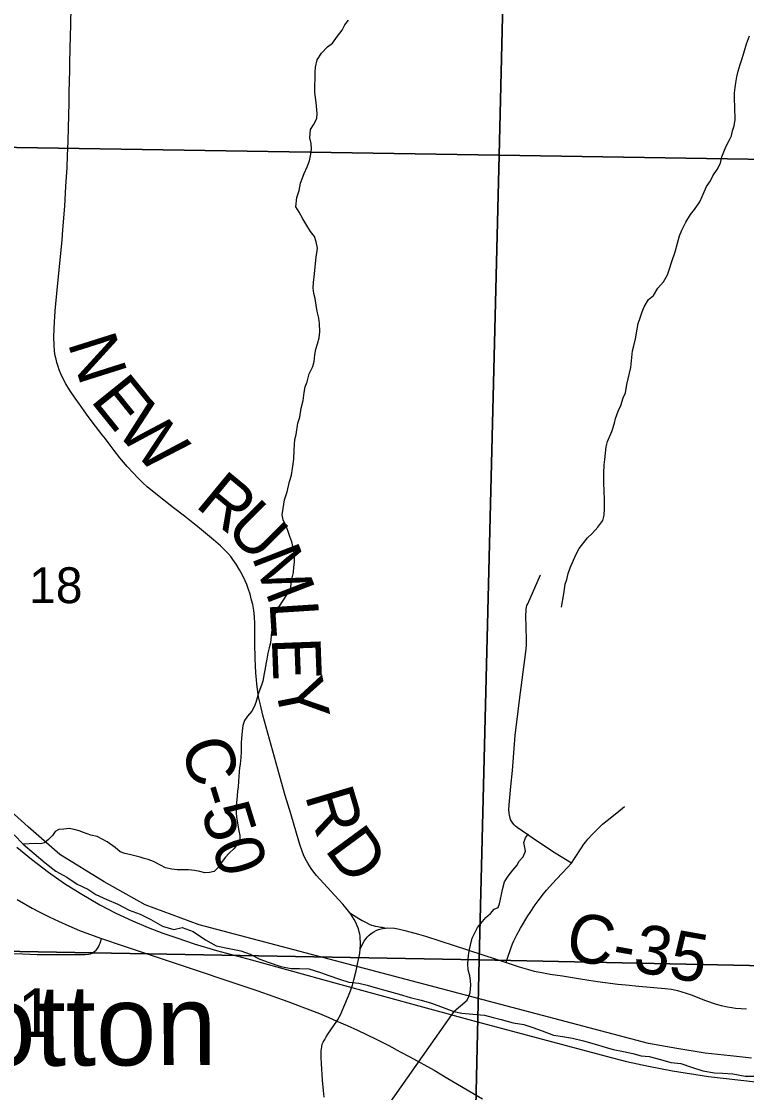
# Model space of a CAD drawing. Extents: x 0 to 34, y 0 to 22.
# Drawn here: x 12.938 to 13.784, y 17.845 to 19.096 of the extents above; entities that cross this region are included whole.
import ezdxf

# ---------------------------------------------------------------- set-up
doc = ezdxf.new("R2010")
doc.units = 0
for name, color, linetype in [('GM_X_Corporation', 7, 'Continuous'), ('GM_X_County_Road', 7, 'Continuous'), ('GM_X_County_Road_Text', 7, 'Continuous'), ('GM_X_Major_River', 7, 'Continuous'), ('GM_X_Major_River_Text', 7, 'Continuous'), ('GM_X_Minor_River', 7, 'Continuous'), ('GM_X_Rail_Line', 7, 'Continuous'), ('GM_X_Section_Text', 7, 'Continuous'), ('GM_X_State_Route', 7, 'Continuous'), ('GM_X_Township_Road', 7, 'Continuous'), ('GM_X_Township_Road_Text', 7, 'Continuous')]:
    doc.layers.add(name, color=color, linetype=linetype)

msp = doc.modelspace()

# ---------------------------------------------------------------- linework, layer by layer
at = {"layer": 'GM_X_Corporation'}
for points in [[(13.52, 19.9573), (13.4956, 18.9396), (12.4906, 18.9558), (12.5051, 19.9749)], [(14.532, 19.9321), (14.5125, 18.9236), (13.4956, 18.9396), (13.52, 19.9573)], [(12.4906, 18.9558), (13.4956, 18.9396), (13.4723, 18.0001), (12.4638, 18.0185)], [(13.4956, 18.9396), (14.5125, 18.9236), (14.4926, 17.9788), (13.4723, 18.0001)], [(12.4638, 18.0185), (13.4723, 18.0001), (13.4493, 16.9912), (12.4446, 17.0089)], [(13.4723, 18.0001), (14.4926, 17.9788), (14.4709, 16.9847), (13.4493, 16.9912)]]:
    msp.add_lwpolyline(points, close=True, dxfattribs=at)
at = {"layer": 'GM_X_County_Road'}
for points in [[(13.2879, 17.8943), (13.288, 17.8961), (13.2884, 17.8992), (13.2891, 17.9017), (13.2902, 17.9042), (13.2919, 17.9074), (13.2935, 17.9103), (13.2956, 17.9135), (13.3059, 17.9286), (13.3075, 17.9311), (13.3088, 17.9334), (13.3102, 17.936), (13.3143, 17.9452), (13.3197, 17.9581), (13.3219, 17.9641), (13.3242, 17.9706), (13.3259, 17.9768), (13.3287, 17.9874), (13.3307, 17.9973), (13.3324, 18.0059), (13.3327, 18.008), (13.3332, 18.0126), (13.3336, 18.0183), (13.3333, 18.0277), (13.3329, 18.0301), (13.3323, 18.033), (13.3312, 18.0365), (13.3298, 18.04), (13.3282, 18.0437), (13.3263, 18.0472), (13.3225, 18.0534), (13.3212, 18.0552), (13.3151, 18.0628), (13.3129, 18.0653), (13.2991, 18.0803), (13.2823, 18.0987), (13.2791, 18.1028), (13.2762, 18.1067), (13.2722, 18.1131), (13.2692, 18.1184), (13.2671, 18.123), (13.2655, 18.1273), (13.2628, 18.1351), (13.259, 18.1483), (13.2527, 18.1695), (13.2459, 18.192), (13.2412, 18.2089), (13.2197, 18.2859), (13.2169, 18.2981), (13.2148, 18.3075), (13.2134, 18.3164), (13.2127, 18.3223), (13.2121, 18.3276), (13.2115, 18.3349), (13.2107, 18.3524), (13.2104, 18.3691), (13.2103, 18.3929), (13.2099, 18.4008), (13.2091, 18.4082), (13.2079, 18.4152), (13.2066, 18.4202), (13.2047, 18.4273), (13.2031, 18.4325), (13.2009, 18.4385), (13.1991, 18.4428), (13.1956, 18.4501), (13.1924, 18.4558), (13.1884, 18.4624), (13.1847, 18.4677), (13.1822, 18.471), (13.1788, 18.4749), (13.1746, 18.4794), (13.1701, 18.4837), (13.1622, 18.4907), (13.1457, 18.5041), (13.1281, 18.5183), (13.1152, 18.528), (13.0948, 18.5442), (13.0848, 18.5525), (13.0797, 18.5571), (13.073, 18.5637), (13.0686, 18.5684), (13.0612, 18.5761), (13.0527, 18.5864), (13.046, 18.5951), (13.0414, 18.6011), (13.036, 18.6084), (13.0323, 18.6133), (13.0245, 18.6234), (13.0159, 18.6348), (13.011, 18.6413), (13.0055, 18.6489), (13.0005, 18.6559), (12.9939, 18.6658), (12.9897, 18.6728), (12.987, 18.6778), (12.9838, 18.6845), (12.982, 18.6891), (12.9806, 18.6932), (12.9792, 18.6978), (12.9783, 18.7017), (12.9774, 18.7055), (12.9766, 18.7108), (12.976, 18.7179), (12.9758, 18.7278), (12.9764, 18.7457), (12.9768, 18.7506), (12.9773, 18.7579), (12.98, 18.7865), (12.9854, 18.8407), (12.9864, 18.8525), (12.9884, 18.8803), (12.9897, 18.9032), (12.9912, 18.9252), (12.9916, 18.9392), (12.9923, 18.9556), (12.9929, 18.9719), (12.9932, 18.9858), (12.9935, 19.0016), (12.9937, 19.0131), (12.994, 19.0266), (12.9943, 19.0387), (12.9943, 19.0471), (12.9946, 19.0646), (12.995, 19.0784), (12.9954, 19.0923), (12.9962, 19.1338)], [(13.3212, 18.0552), (13.3231, 18.054), (13.3255, 18.0525), (13.3316, 18.0487), (13.3355, 18.0463), (13.3404, 18.0437), (13.3439, 18.042), (13.3467, 18.0409), (13.3484, 18.0403), (13.3508, 18.0396), (13.3539, 18.039), (13.357, 18.0385), (13.3591, 18.0382), (13.363, 18.0374)], [(13.3332, 18.0126), (13.335, 18.0161), (13.338, 18.0221), (13.34, 18.0249), (13.3419, 18.0271), (13.3439, 18.0292), (13.3461, 18.031), (13.3493, 18.033), (13.3519, 18.0346), (13.3548, 18.0358), (13.3578, 18.0366), (13.3593, 18.037), (13.3618, 18.0373), (13.363, 18.0374), (13.3654, 18.0375), (13.3733, 18.0371), (13.3791, 18.0361), (13.3855, 18.0345), (13.3914, 18.0331), (13.4015, 18.0302), (13.4094, 18.0278), (13.4431, 18.017), (13.4585, 18.0121), (13.4764, 18.0062), (13.492, 18.0011), (13.5038, 17.9972), (13.519, 17.9921), (13.5297, 17.9889), (13.5362, 17.9872), (13.5452, 17.9854), (13.5552, 17.9836), (13.5696, 17.9814), (13.5903, 17.9782), (13.6001, 17.9766), (13.6103, 17.975), (13.6339, 17.972), (13.6433, 17.9709), (13.6586, 17.9696), (13.6892, 17.9669), (13.6966, 17.966), (13.7036, 17.9644), (13.7089, 17.963), (13.7139, 17.9612), (13.7195, 17.9594), (13.7365, 17.9529), (13.7488, 17.9485), (13.7547, 17.9469), (13.762, 17.9453), (13.767, 17.9444), (13.7715, 17.9438), (13.7779, 17.9433), (13.7844, 17.943)], [(13.2911, 17.8399), (13.2904, 17.8477), (13.2895, 17.8597), (13.2881, 17.8791), (13.2878, 17.8861), (13.2879, 17.8943)]]:
    msp.add_lwpolyline(points, dxfattribs=at)
at = {"layer": 'GM_X_Major_River'}
msp.add_lwpolyline([(12.9293, 18.1462), (12.9401, 18.1353), (12.9528, 18.1245), (12.9655, 18.1134), (12.9782, 18.1037), (12.9908, 18.0967), (13.003, 18.0886), (13.0153, 18.0827), (13.0248, 18.0764), (13.0375, 18.0706), (13.0504, 18.0651), (13.0638, 18.0581), (13.0764, 18.0534), (13.089, 18.0475), (13.1024, 18.0394), (13.1157, 18.0358), (13.1256, 18.0379), (13.1385, 18.0332), (13.1527, 18.0235), (13.1653, 18.0165), (13.1802, 18.0134), (13.1938, 18.0109), (13.2049, 18.0069), (13.216, 18.0011), (13.2259, 17.9974), (13.2408, 17.9924), (13.2529, 17.9903), (13.2624, 17.9901), (13.2734, 17.9899), (13.2868, 17.9855), (13.2967, 17.9819), (13.3092, 17.9776), (13.3199, 17.974), (13.3317, 17.973), (13.3416, 17.9705), (13.3534, 17.9673), (13.3675, 17.9634), (13.3789, 17.9601), (13.3915, 17.9562), (13.4044, 17.953), (13.4166, 17.9498), (13.4303, 17.9447), (13.4425, 17.9399), (13.452, 17.9378), (13.4646, 17.9369), (13.4786, 17.9356), (13.4885, 17.9331), (13.498, 17.9306), (13.5117, 17.9267), (13.5243, 17.9246), (13.5349, 17.9214), (13.5456, 17.9174), (13.559, 17.9123), (13.5696, 17.9106), (13.581, 17.9089), (13.594, 17.9057), (13.6065, 17.9021), (13.6191, 17.8981), (13.6286, 17.8956), (13.6408, 17.8932), (13.6514, 17.8907), (13.6613, 17.8882), (13.6708, 17.8872), (13.6838, 17.884), (13.696, 17.8804), (13.7074, 17.8791), (13.7199, 17.8751), (13.7333, 17.8708), (13.7469, 17.8684), (13.7564, 17.8678), (13.7682, 17.8672), (13.7826, 17.8644), (13.7936, 17.8646)], dxfattribs=at)
at = {"layer": 'GM_X_Minor_River'}
for points in [[(13.2348, 18.4064), (13.2518, 18.4332), (13.2534, 18.4449), (13.2553, 18.4525), (13.2557, 18.4586), (13.2565, 18.4647), (13.2566, 18.4738), (13.2536, 18.4883), (13.251, 18.4947), (13.2491, 18.5004), (13.2468, 18.5065), (13.2434, 18.5138), (13.2423, 18.5198), (13.2435, 18.5274), (13.2451, 18.5373), (13.2481, 18.5468), (13.2509, 18.5586), (13.2532, 18.5662), (13.2543, 18.5738), (13.2559, 18.5848), (13.2563, 18.5954), (13.2571, 18.6076), (13.2587, 18.6136), (13.2606, 18.6269), (13.2629, 18.6338), (13.2645, 18.6444), (13.2668, 18.6535), (13.268, 18.6626), (13.2692, 18.6691), (13.2715, 18.6751), (13.2738, 18.6843), (13.278, 18.693), (13.2795, 18.6987), (13.2803, 18.7067), (13.2815, 18.7131), (13.2834, 18.7196), (13.2853, 18.7264), (13.2861, 18.7336), (13.2858, 18.7431), (13.2851, 18.7496), (13.2836, 18.7557), (13.2825, 18.7621), (13.2806, 18.7724), (13.2791, 18.7781), (13.2784, 18.7846), (13.2788, 18.791), (13.28, 18.8013), (13.2808, 18.8093), (13.282, 18.8206), (13.2835, 18.8313), (13.282, 18.8385), (13.2798, 18.845), (13.2753, 18.8507), (13.2711, 18.8575), (13.2662, 18.8655), (13.2621, 18.8732), (13.2583, 18.8796), (13.2595, 18.8903), (13.2622, 18.8986), (13.2637, 18.907), (13.268, 18.9184), (13.2714, 18.9263), (13.2741, 18.9332), (13.2756, 18.9411), (13.2764, 18.9468), (13.2761, 18.9533), (13.2746, 18.9601), (13.2754, 18.9696), (13.2788, 18.9753), (13.2827, 18.9825), (13.2831, 18.9886), (13.282, 19.0011), (13.2805, 19.0129), (13.2802, 19.0201), (13.2806, 19.03), (13.2806, 19.0369), (13.281, 19.0426), (13.283, 19.0509), (13.2883, 19.0589), (13.2952, 19.0664), (13.3009, 19.0706), (13.307, 19.0789), (13.3123, 19.0858), (13.3154, 19.0918), (13.3196, 19.0975)], [(13.5682, 18.4119), (13.5709, 18.4275), (13.5725, 18.4388), (13.5744, 18.4445), (13.5759, 18.4514), (13.5783, 18.4578), (13.5851, 18.473), (13.589, 18.4806), (13.5985, 18.4931), (13.6042, 18.498), (13.6107, 18.5056), (13.6164, 18.5132), (13.618, 18.5196), (13.6184, 18.5268), (13.6184, 18.5371), (13.6181, 18.5485), (13.6178, 18.5561), (13.6178, 18.5686), (13.6182, 18.5781), (13.619, 18.5846), (13.6198, 18.5918), (13.6206, 18.5994), (13.6218, 18.6055), (13.6271, 18.6172), (13.6302, 18.6267), (13.6314, 18.6324), (13.6344, 18.6408), (13.6375, 18.6476), (13.6402, 18.6563), (13.6429, 18.6624), (13.6444, 18.6719), (13.646, 18.6787), (13.6491, 18.692), (13.6511, 18.7114), (13.6526, 18.7171), (13.6545, 18.7254), (13.6565, 18.7368), (13.6576, 18.7433), (13.66, 18.7497), (13.6626, 18.7569), (13.6649, 18.7626), (13.6699, 18.7714), (13.6756, 18.7759), (13.6806, 18.7846), (13.6875, 18.7918), (13.692, 18.8002), (13.6943, 18.807), (13.697, 18.8157), (13.7009, 18.8271), (13.7036, 18.837), (13.7059, 18.8457), (13.7086, 18.8522), (13.7136, 18.8616), (13.7189, 18.8704), (13.7235, 18.8764), (13.7296, 18.8851), (13.7323, 18.8916), (13.7376, 18.903), (13.7422, 18.9098), (13.7449, 18.9155), (13.7499, 18.9231), (13.7537, 18.9303), (13.7556, 18.9379), (13.7602, 18.9496), (13.7641, 18.9568), (13.7667, 18.9625), (13.7679, 18.9682), (13.7698, 18.9739), (13.771, 18.9815), (13.7707, 18.9956), (13.7703, 19.0062), (13.7704, 19.0127), (13.7711, 19.0187), (13.7719, 19.0244), (13.7731, 19.0313), (13.7746, 19.0377), (13.777, 19.0457), (13.7789, 19.0514), (13.7808, 19.0579), (13.7843, 19.0696), (13.7877, 19.0791)], [(13.2348, 18.4064), (13.2329, 18.4003), (13.2311, 18.3881), (13.2299, 18.3828), (13.2285, 18.3703), (13.227, 18.3646), (13.2255, 18.3585), (13.2244, 18.3513), (13.2232, 18.3456), (13.2225, 18.3406), (13.2214, 18.3346), (13.2195, 18.3258), (13.218, 18.3209), (13.2161, 18.3159), (13.2142, 18.3106), (13.2131, 18.3061), (13.2116, 18.3008), (13.2097, 18.2958), (13.2067, 18.2905), (13.2018, 18.2848), (13.1984, 18.2798), (13.1965, 18.2738), (13.1954, 18.2673), (13.1947, 18.2586), (13.1943, 18.254), (13.1944, 18.2434), (13.194, 18.2365), (13.1933, 18.2289), (13.1925, 18.2244), (13.1922, 18.2198), (13.1918, 18.2145), (13.1914, 18.2088), (13.1907, 18.202), (13.19, 18.1974), (13.1896, 18.1917), (13.1885, 18.1796), (13.1885, 18.172), (13.1889, 18.1667), (13.1916, 18.1507), (13.1928, 18.1454), (13.1928, 18.1409), (13.1898, 18.1348), (13.1864, 18.1302), (13.1803, 18.1249), (13.1758, 18.1199), (13.1713, 18.1139), (13.1683, 18.1089), (13.163, 18.1032), (13.1576, 18.1024), (13.1519, 18.102), (13.1463, 18.1032), (13.1398, 18.1047), (13.133, 18.1054), (13.1197, 18.1054), (13.1136, 18.1061), (13.106, 18.1077), (13.1003, 18.1107), (13.0919, 18.1152), (13.0858, 18.1175), (13.0813, 18.1186), (13.0763, 18.1201), (13.0642, 18.1231), (13.0585, 18.1243), (13.0532, 18.1265), (13.0474, 18.1315), (13.0379, 18.1379), (13.0261, 18.1443), (13.0189, 18.1459), (13.0105, 18.1489), (13.0052, 18.1508), (12.9995, 18.1523), (12.9935, 18.1534), (12.9874, 18.153), (12.9817, 18.1526), (12.9771, 18.1499), (12.9741, 18.1454), (12.9696, 18.1408), (12.9647, 18.137), (12.9601, 18.1355), (12.954, 18.1362), (12.9401, 18.1353)], [(13.4425, 17.9399), (13.4581, 17.953), (13.46, 17.9576), (13.4615, 17.9621), (13.4626, 17.9705), (13.4622, 17.9762), (13.4614, 17.9815), (13.4595, 17.9887), (13.4591, 17.9955), (13.4598, 18.0058), (13.4609, 18.0122), (13.462, 18.0172), (13.4639, 18.0255), (13.4677, 18.0324), (13.4703, 18.0381), (13.476, 18.0449), (13.4798, 18.0495), (13.4855, 18.0544), (13.4896, 18.0594), (13.4942, 18.0613), (13.496, 18.0658), (13.4983, 18.0765), (13.4994, 18.0822), (13.5017, 18.0913), (13.5062, 18.0978), (13.5115, 18.105), (13.5164, 18.1107), (13.5183, 18.1152), (13.5236, 18.1206), (13.5262, 18.127), (13.5254, 18.1316), (13.5243, 18.1373), (13.5262, 18.1426), (13.5296, 18.1475)], [(13.4425, 17.9399), (13.3436, 17.7994)]]:
    msp.add_lwpolyline(points, dxfattribs=at)
at = {"layer": 'GM_X_Rail_Line'}
for points in [[(13.7901, 17.8853), (13.7655, 17.888), (13.736, 17.8911), (13.7029, 17.8967), (13.67, 17.9025), (13.1455, 18.041), (13.0824, 18.0646), (13.0345, 18.0914), (12.9829, 18.1233), (12.9459, 18.1554), (12.8969, 18.1997)], [(12.9327, 18.1319), (12.9496, 18.1177), (12.9694, 18.1025), (12.988, 18.0894), (13.0063, 18.0779), (13.0295, 18.0645), (13.0481, 18.0548), (13.0674, 18.0457), (13.0857, 18.038), (13.1031, 18.0312), (13.1192, 18.0258), (13.1394, 18.019), (13.1657, 18.0112), (13.2064, 18.0001), (13.3021, 17.9738), (13.4644, 17.9296), (13.6203, 17.8876), (13.6443, 17.8816), (13.6697, 17.876), (13.6979, 17.8706), (13.74, 17.864), (13.7948, 17.8578)]]:
    msp.add_lwpolyline(points, dxfattribs=at)
at = {"layer": 'GM_X_State_Route'}
msp.add_lwpolyline([(12.9328, 18.0705), (12.9504, 18.0607), (12.9587, 18.0561), (12.971, 18.0499), (12.9813, 18.0452), (12.9933, 18.0398), (13.0057, 18.0346), (13.0175, 18.0301), (13.0315, 18.0251), (13.0567, 18.0165), (13.1348, 17.9905), (13.1869, 17.9731), (13.2137, 17.9642), (13.249, 17.9517), (13.2684, 17.9442), (13.2857, 17.9375), (13.2969, 17.9328), (13.3059, 17.9286), (13.3183, 17.9235), (13.3302, 17.918), (13.3519, 17.9076), (13.3667, 17.9001), (13.38, 17.893), (13.3914, 17.887), (13.4195, 17.8713), (13.4358, 17.8617), (13.4761, 17.8379)], dxfattribs=at)
at = {"layer": 'GM_X_Township_Road'}
for points in [[(13.5798, 18.1131), (13.561, 18.1246), (13.5404, 18.1384), (13.5165, 18.1546), (13.5144, 18.1563), (13.513, 18.1577), (13.5114, 18.1597), (13.5099, 18.162), (13.5089, 18.164), (13.5082, 18.1662), (13.5076, 18.1687), (13.5071, 18.1717), (13.5069, 18.1755), (13.5073, 18.1812), (13.508, 18.1897), (13.5092, 18.2025), (13.5109, 18.2214), (13.5134, 18.2522), (13.5143, 18.2626), (13.5164, 18.281), (13.5193, 18.3036), (13.5266, 18.3597), (13.5273, 18.3673), (13.5274, 18.3732), (13.527, 18.3894), (13.5267, 18.4013), (13.527, 18.4094), (13.5273, 18.4121), (13.5279, 18.4139), (13.5288, 18.416), (13.5439, 18.4499)], [(13.5038, 17.9972), (13.505, 18.0012), (13.5094, 18.0148), (13.5109, 18.0188), (13.5125, 18.0225), (13.5163, 18.0296), (13.5206, 18.0371), (13.5291, 18.0515), (13.5316, 18.0555), (13.5376, 18.0645), (13.541, 18.0691), (13.5472, 18.0773), (13.5507, 18.0816), (13.5581, 18.0899), (13.5619, 18.094), (13.5699, 18.1022), (13.5798, 18.1131), (13.5836, 18.1185), (13.5917, 18.1311), (13.5943, 18.1352), (13.5965, 18.1382), (13.599, 18.1413), (13.604, 18.1465), (13.6121, 18.1546), (13.6163, 18.1585), (13.6216, 18.1629), (13.6327, 18.1717), (13.6419, 18.1792)], [(12.9155, 18.0079), (12.9391, 18.0071), (12.9563, 18.0066), (13.0065, 18.0063), (13.0121, 18.0065), (13.0162, 18.0069), (13.0185, 18.0074), (13.0206, 18.0082), (13.0221, 18.0091), (13.0237, 18.0103), (13.0251, 18.0117), (13.0266, 18.0136), (13.0279, 18.0156), (13.0291, 18.0182), (13.0298, 18.0199), (13.031, 18.0235), (13.0315, 18.0251)]]:
    msp.add_lwpolyline(points, dxfattribs=at)

# ---------------------------------------------------------------- texts
at = {"layer": 'GM_X_County_Road_Text'}
for s, height, rotation, p in [('N', 0.0568, 287.5503, (12.9916, 18.7208)), ('E', 0.0568, 308.8793, (13.0174, 18.6533)), ('W', 0.0568, 312.3738, (13.0465, 18.6174)), ('R', 0.0568, 320.4618, (13.1394, 18.5302)), ('U', 0.0568, 314.8764, (13.1743, 18.5015)), ('M', 0.0568, 291.1109, (13.2062, 18.4712)), ('L', 0.0568, 273.6667, (13.2274, 18.4181)), ('E', 0.0568, 272.139, (13.2301, 18.3761)), ('Y', 0.0568, 281.4362, (13.2329, 18.3238)), ('C-50', 0.05682, 287.251, (13.1233, 18.2509)), ('R', 0.0568, 286.5796, (13.2684, 18.1925)), ('D', 0.0568, 306.3199, (13.291, 18.129)), ('C-35', 0.05682, 349.8911, (13.5711, 18.0013))]:
    msp.add_text(s, height=height, rotation=rotation, dxfattribs=at).set_placement(p)
at = {"layer": 'GM_X_Major_River_Text'}
msp.add_text('Conotton', height=0.0947, rotation=0.3119, dxfattribs=at).set_placement((12.652, 17.8748))
at = {"layer": 'GM_X_Section_Text'}
msp.add_text('18', height=0.04186, rotation=0, dxfattribs=at).set_placement((12.9469, 18.4167))
at = {"layer": 'GM_X_Township_Road_Text'}
msp.add_text('1', height=0.0568, rotation=359.95, dxfattribs=at).set_placement((12.9335, 17.9101))

doc.saveas('drawing.dxf')
